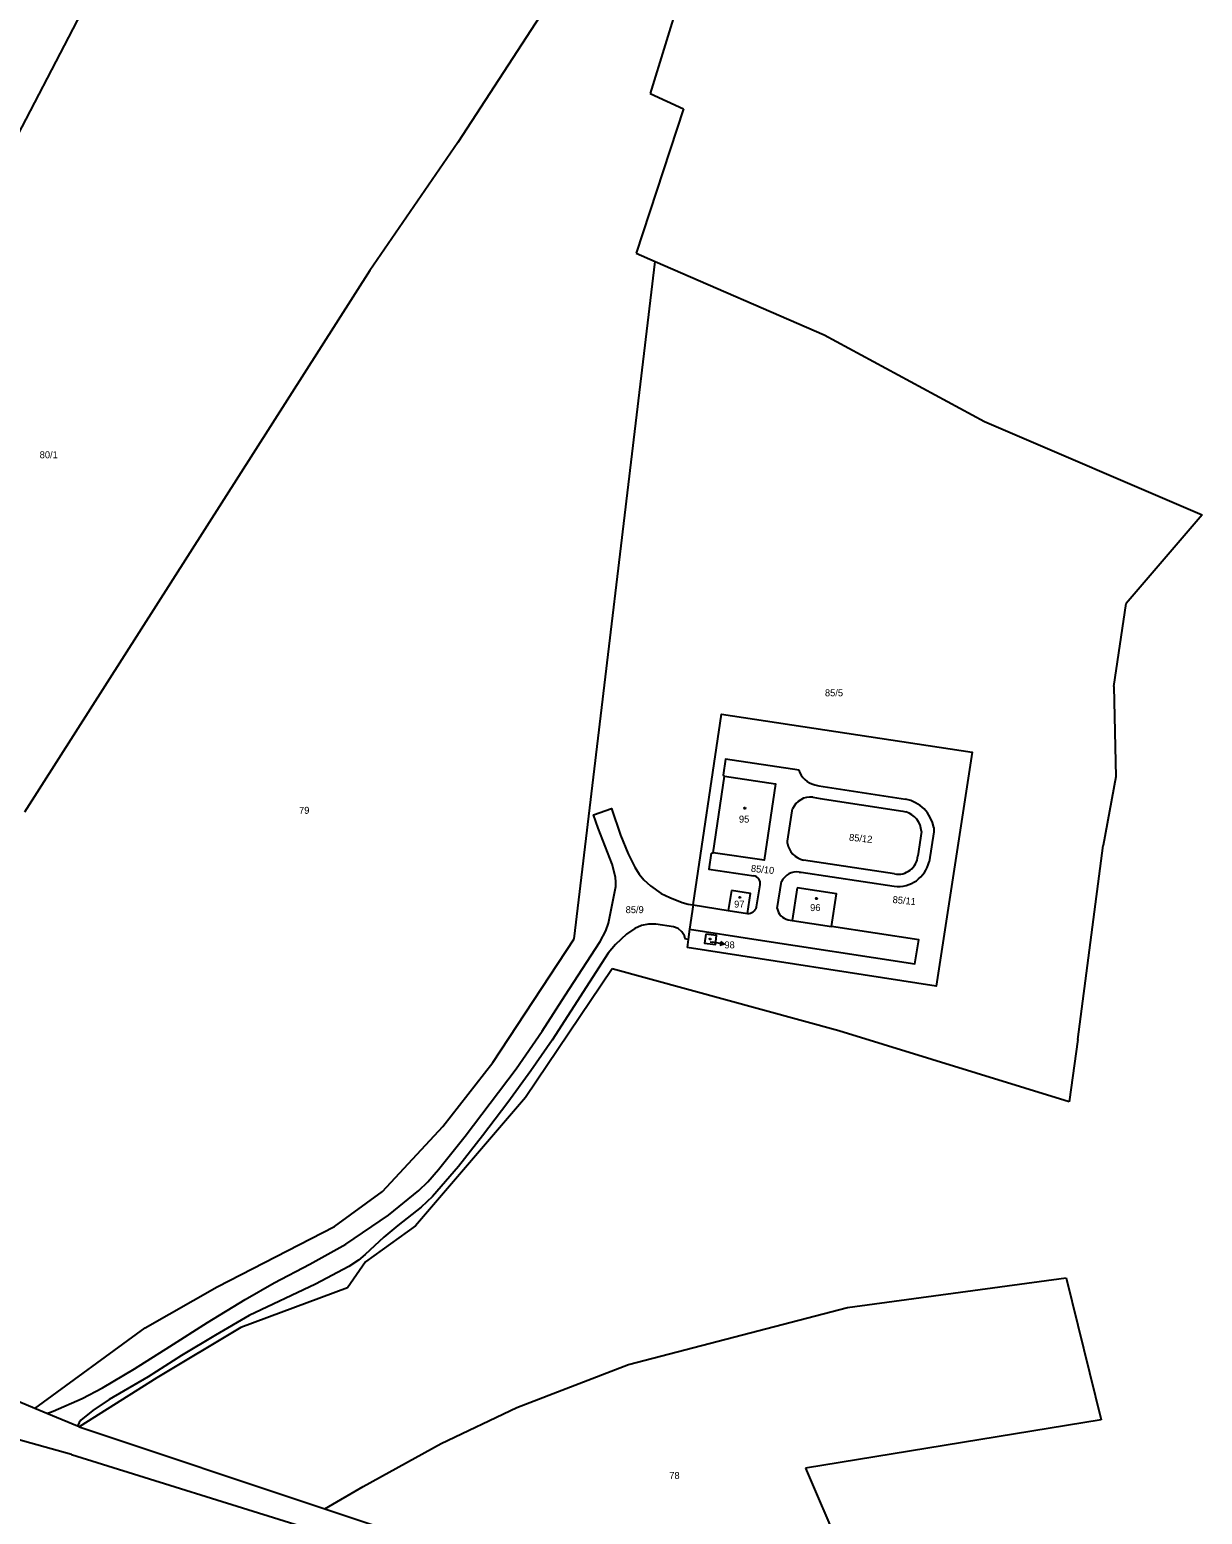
# Model space of a CAD drawing. Extents: x -752343 to -750336, y -1035826 to -1033329.
# Drawn here: x -750903.1 to -750616.5, y -1035099 to -1034736.3 of the extents above; entities that cross this region are included whole.
import ezdxf

# ---------------------------------------------------------------- set-up
doc = ezdxf.new("R2010")
doc.units = 0
for name, color, linetype in [('Default', 7, 'Continuous'), ('KN_HRANICE', 7, 'Continuous'), ('KN_KULTURY', 7, 'Continuous'), ('KN_PARCELY', 7, 'Continuous')]:
    doc.layers.add(name, color=color, linetype=linetype)

# ---------------------------------------------------------------- blocks, each defined once
blk = doc.blocks.new('10292')
at = {"layer": 'Default'}
blk.add_line((0, 3), (0, 0), dxfattribs=at)
blk.add_lwpolyline([(-0.5, 2), (0, 3), (0.5, 2)], dxfattribs=at)
blk = doc.blocks.new('402')
at = {"layer": 'Default'}
blk.add_lwpolyline([(0.09, 0.15), (0.18, 0), (0.09, -0.15), (-0.09, -0.15), (-0.18, 0), (-0.09, 0.15), (0.09, 0.15)], dxfattribs=at)

msp = doc.modelspace()

# ---------------------------------------------------------------- linework, layer by layer
at = {"layer": 'KN_HRANICE'}
for p, q in [((-750735.8, -1034701.33), (-750751.48, -1034751.87)), ((-750885.14, -1034721.76), (-750921.44, -1034791.39)), ((-750776.12, -1034729.56), (-750798.43, -1034763.86)), ((-750751.48, -1034751.87), (-750743.26, -1034755.6)), ((-750743.26, -1034755.6), (-750754.83, -1034790.88)), ((-750798.43, -1034763.86), (-750819.97, -1034795.13)), ((-750754.83, -1034790.88), (-750750.21, -1034792.89)), ((-750770.01, -1034958.43), (-750750.21, -1034792.89)), ((-750750.21, -1034792.89), (-750708.89, -1034810.84)), ((-750819.97, -1034795.13), (-750904.38, -1034927.42)), ((-750708.89, -1034810.84), (-750669.68, -1034832)), ((-750669.68, -1034832), (-750616.47, -1034854.77)), ((-750616.47, -1034854.77), (-750635.06, -1034876.44)), ((-750638.09, -1034896.73), (-750635.06, -1034876.44)), ((-750638.09, -1034896.73), (-750637.62, -1034918.84)), ((-750736.05, -1034937.36), (-750733.24, -1034918.68)), ((-750733.24, -1034918.68), (-750733.62, -1034918.42)), ((-750637.62, -1034918.84), (-750640.67, -1034935.58)), ((-750685.15, -1034932.21), (-750686.02, -1034938.16)), ((-750646.9, -1034982.97), (-750640.67, -1034935.58)), ((-750736.5, -1034937.5), (-750736.05, -1034937.36)), ((-750691.71, -1034942.55), (-750713.95, -1034939.17)), ((-750731.56, -1034946.57), (-750732.36, -1034951.5)), ((-750725.42, -1034950.63), (-750724.55, -1034945.2)), ((-750720.39, -1034951.03), (-750719.32, -1034944.37)), ((-750715.53, -1034945.96), (-750716.75, -1034953.93)), ((-750740.97, -1034950.11), (-750741.85, -1034956.05)), ((-750740.97, -1034950.11), (-750732.36, -1034951.5)), ((-750732.36, -1034951.5), (-750727.63, -1034952.24)), ((-750717.73, -1034953.73), (-750716.75, -1034953.93)), ((-750716.75, -1034953.93), (-750707.09, -1034955.39)), ((-750741.85, -1034956.05), (-750742.17, -1034958.57)), ((-750789.92, -1034988.62), (-750770.01, -1034958.43)), ((-750742.17, -1034958.57), (-750742.43, -1034960.56)), ((-750760.75, -1034965.71), (-750781.93, -1034997.22)), ((-750705.36, -1034980.91), (-750760.75, -1034965.71)), ((-750648.98, -1034998.22), (-750705.36, -1034980.91)), ((-750646.9, -1034982.97), (-750648.98, -1034998.22)), ((-750802.11, -1035004.29), (-750789.92, -1034988.62)), ((-750781.93, -1034997.22), (-750808.77, -1035028.55)), ((-750816.84, -1035020.15), (-750802.11, -1035004.29)), ((-750828.63, -1035028.73), (-750816.84, -1035020.15)), ((-750857.32, -1035043.41), (-750828.63, -1035028.73)), ((-750808.77, -1035028.55), (-750821.04, -1035037.35)), ((-750821.04, -1035037.35), (-750825.43, -1035043.68)), ((-750703.19, -1035048.53), (-750649.72, -1035041.28)), ((-750649.72, -1035041.28), (-750641.2, -1035075.94)), ((-750874.87, -1035053.45), (-750857.32, -1035043.41)), ((-750825.43, -1035043.68), (-750851.53, -1035053.36)), ((-750756.76, -1035062.46), (-750703.19, -1035048.53)), ((-750901.86, -1035073.17), (-750874.87, -1035053.45)), ((-750851.53, -1035053.36), (-750872, -1035065.71)), ((-750901.86, -1035073.17), (-750936.07, -1035058.92)), ((-750784.02, -1035072.94), (-750756.76, -1035062.46)), ((-750872, -1035065.71), (-750891.06, -1035077.67)), ((-750898.92, -1035074.4), (-750901.86, -1035073.17)), ((-750802.56, -1035081.72), (-750784.02, -1035072.94)), ((-750892.88, -1035084.41), (-750919.78, -1035076.95)), ((-750891.45, -1035077.51), (-750898.92, -1035074.4)), ((-750891.06, -1035077.67), (-750891.45, -1035077.51)), ((-750641.2, -1035075.94), (-750713.44, -1035087.79)), ((-750891.06, -1035077.67), (-750830.94, -1035097.68)), ((-750892.88, -1035084.41), (-750833.35, -1035102.98)), ((-750821.62, -1035092.2), (-750802.56, -1035081.72)), ((-750713.44, -1035087.79), (-750688.06, -1035146.89)), ((-750830.94, -1035097.68), (-750821.62, -1035092.2)), ((-750830.94, -1035097.68), (-750799.07, -1035108.28))]:
    msp.add_line(p, q, dxfattribs=at)
for points in [[(-750740.97, -1034950.11), (-750734.04, -1034903.51), (-750672.73, -1034912.81), (-750681.57, -1034970), (-750742.43, -1034960.56)], [(-750715.06, -1034917.19), (-750733.02, -1034914.51), (-750733.62, -1034918.42)], [(-750733.24, -1034918.68), (-750720.77, -1034920.56), (-750723.57, -1034939.2), (-750736.05, -1034937.36)], [(-750711.21, -1034920.76), (-750710.23, -1034920.99), (-750689.04, -1034924.29)], [(-750711.7, -1034923.78), (-750709.91, -1034924.09), (-750689.67, -1034927.21), (-750688.94, -1034927.4)], [(-750898.92, -1035074.4), (-750897.41, -1035073.81), (-750890.32, -1035070.72), (-750885.35, -1035068.16), (-750877.46, -1035063.5), (-750868.82, -1035058.04), (-750859.66, -1035052.19), (-750850.44, -1035046.52), (-750843.34, -1035042.48), (-750834.62, -1035037.88), (-750825.86, -1035033.03), (-750815.39, -1035025.94), (-750807.98, -1035019.93), (-750805.82, -1035017.82), (-750803.21, -1035014.81), (-750796.68, -1035006.65), (-750790.52, -1034998.59), (-750784.17, -1034990.17), (-750777.83, -1034980.99), (-750772.33, -1034972.32), (-750763.63, -1034959.06), (-750762.25, -1034956.42), (-750761.6, -1034954.55), (-750759.81, -1034945.62), (-750759.81, -1034944.56), (-750759.94, -1034943.36), (-750760.73, -1034940.14), (-750764.17, -1034931.4), (-750765.32, -1034928.13), (-750760.93, -1034926.58), (-750758.7, -1034933.05), (-750756.82, -1034937.65), (-750755.21, -1034940.88), (-750754.13, -1034942.57), (-750752.96, -1034944.03), (-750751.34, -1034945.44), (-750748.79, -1034947.3), (-750746.6, -1034948.31), (-750743.6, -1034949.53), (-750742.19, -1034949.94), (-750741.62, -1034950.01), (-750740.97, -1034950.11)], [(-750717.87, -1034935.08), (-750717.86, -1034934.58), (-750716.76, -1034927.15), (-750716.64, -1034926.67)], [(-750682.13, -1034931.24), (-750682.12, -1034932.24), (-750683.25, -1034939.59)], [(-750736.5, -1034937.5), (-750737.1, -1034941.42), (-750726.14, -1034942.99)], [(-750715.01, -1034942.08), (-750714.51, -1034942.11), (-750691.76, -1034945.57)], [(-750727.63, -1034952.24), (-750726.88, -1034947.32), (-750731.56, -1034946.57)], [(-750707.09, -1034955.39), (-750705.86, -1034947.4), (-750715.53, -1034945.96)], [(-750742.17, -1034958.57), (-750742.9, -1034958.43), (-750743.08, -1034957.71), (-750743.69, -1034956.69), (-750744.6, -1034955.9), (-750745.72, -1034955.47), (-750750.07, -1034954.85), (-750751.83, -1034954.8), (-750753.57, -1034955.12), (-750755.23, -1034955.85), (-750757.21, -1034957.3), (-750759.93, -1034959.79), (-750761.67, -1034961.93), (-750775.39, -1034983.18), (-750780.59, -1034990.68), (-750786.23, -1034998.38), (-750792.44, -1035006.54), (-750798.27, -1035014.08), (-750804.62, -1035021.34), (-750807.43, -1035023.95), (-750813.15, -1035028.42), (-750816.56, -1035031.28), (-750821.12, -1035035.55), (-750822.71, -1035036.89), (-750825.13, -1035038.47), (-750833.24, -1035042.81), (-750849.48, -1035050.45), (-750857.72, -1035055.23), (-750865.97, -1035060.25), (-750874.16, -1035065.47), (-750883.65, -1035071.01), (-750887.7, -1035073.65), (-750890.61, -1035076.05), (-750891, -1035076.56), (-750891.45, -1035077.51)], [(-750741.85, -1034956.05), (-750726.13, -1034958.47), (-750686.71, -1034964.52), (-750685.78, -1034958.62), (-750707.09, -1034955.39)]]:
    msp.add_lwpolyline(points, dxfattribs=at)
msp.add_lwpolyline([(-750737.85, -1034957.26), (-750738.18, -1034959.45), (-750735.51, -1034959.8), (-750735.22, -1034957.61)], close=True, dxfattribs=at)
for centre, radius, start, end in [((-750710.09, -1034915.69), 5.2, 196.8146, 257.5075), ((-750712.22, -1034928.55), 4.8, 83.7484, 156.9086), ((-750690.54, -1034932.7), 8.54, 9.8134, 79.8559), ((-750690.32, -1034932.39), 5.17, 1.9526, 74.5195), ((-750713, -1034934.33), 4.93, 188.7216, 258.8468), ((-750690.86, -1034937.81), 7.81, 263.3736, 346.818), ((-750690.85, -1034937.78), 4.85, 259.8036, 355.4988), ((-750726.43, -1034944.87), 1.91, 350.1542, 81.3126), ((-750715.53, -1034946.3), 4.25, 82.9278, 153.0377), ((-750727.65, -1034949.89), 2.35, 270.4839, 341.6633), ((-750717.03, -1034950.38), 3.42, 190.9375, 258.2074)]:
    msp.add_arc(centre, radius, start, end, dxfattribs=at)
at = {"layer": 'KN_PARCELY'}
msp.add_line((-750736.77, -1034959.14), (-750736.31, -1034959.22), dxfattribs=at)

# ---------------------------------------------------------------- block references
at = {"layer": 'KN_KULTURY'}
for p in [(-750728.32, -1034926.47), (-750729.51, -1034948.26), (-750710.76, -1034948.56), (-750736.8, -1034958.45)]:
    msp.add_blockref('402', p, dxfattribs=at)
at = {"layer": 'KN_PARCELY', "rotation": -99.36149900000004}
msp.add_blockref('10292', (-750736.31, -1034959.22), dxfattribs=at)

# ---------------------------------------------------------------- texts
at = {"layer": 'KN_PARCELY'}
for s, height, p in [('80/1', 1.7, (-750900.67, -1034840.98)), ('85/5', 1.7, (-750708.72, -1034899.14)), ('79', 1.7, (-750837.27, -1034927.86)), ('95', 1.7, (-750729.74, -1034930.01)), ('85/9', 1.7, (-750757.44, -1034952.13)), ('97', 1.7, (-750730.92, -1034950.78)), ('96', 1.7, (-750712.34, -1034951.63)), ('98', 0.1, (-750736.81, -1034959.16)), ('98', 1.7, (-750733.29, -1034960.74)), ('78', 1.7, (-750746.77, -1035090.39))]:
    msp.add_text(s, height=height, dxfattribs=at).set_placement(p)
for s, p in [('85/12', (-750702.88, -1034934.42)), ('85/10', (-750726.87, -1034942.02)), ('85/11', (-750692.24, -1034949.62))]:
    msp.add_text(s, height=1.7, rotation=354.317, dxfattribs=at).set_placement(p)

doc.saveas('drawing.dxf')
